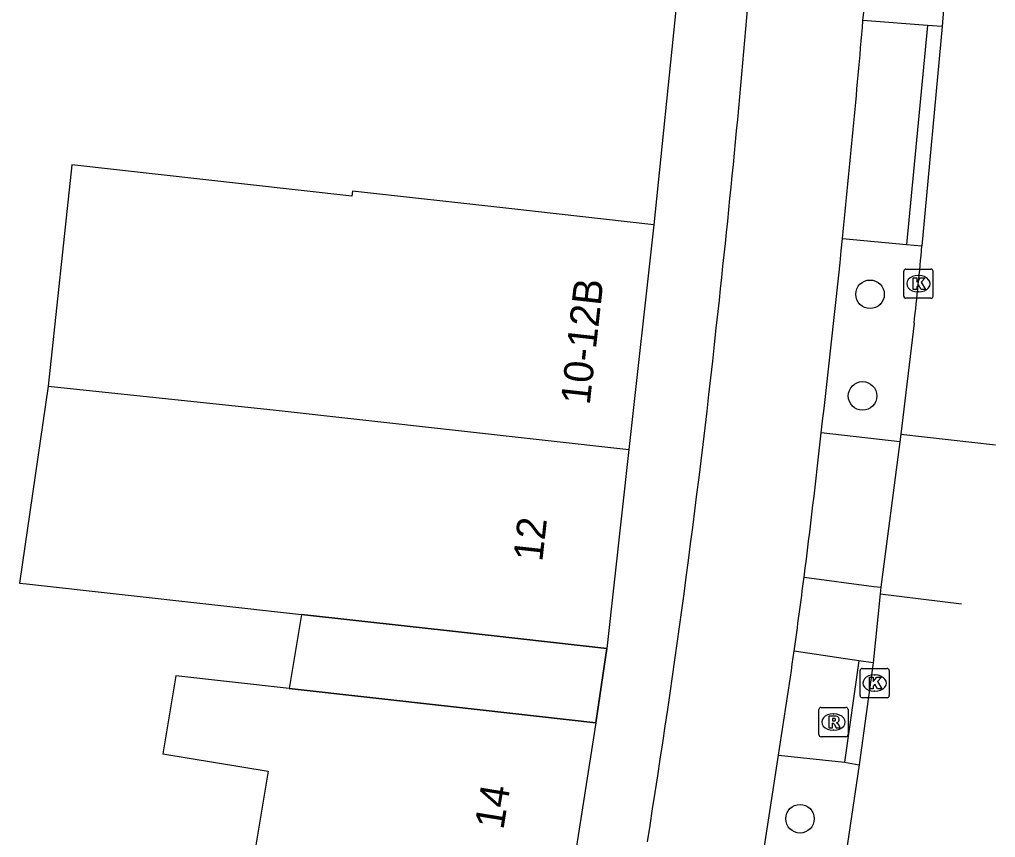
# Model space of a CAD drawing. Extents: x 161087 to 161922, y 382574 to 383873.
# Drawn here: x 161833.12 to 161866.52, y 382703.67 to 382731.66 of the extents above; entities that cross this region are included whole.
import ezdxf

# ---------------------------------------------------------------- set-up
doc = ezdxf.new("R2010")
doc.units = 0
for name, color, linetype in [('IMGEO_Berm_gesloten', 7, 'Continuous'), ('IMGEO_Berm_groen', 7, 'Continuous'), ('IMGEO_Berm_open', 7, 'Continuous'), ('IMGEO_Boom', 7, 'Continuous'), ('IMGEO_Fietspad_gesloten', 7, 'Continuous'), ('IMGEO_Kolk', 7, 'Continuous'), ('IMGEO_Pand', 7, 'Continuous'), ('IMGEO_Pand_nummerreeks', 7, 'Continuous'), ('IMGEO_Pand_overbouw', 7, 'Continuous'), ('IMGEO_Rijbaan_lokaal_gesloten', 7, 'Continuous'), ('IMGEO_Rijbaan_lokaal_open', 7, 'Continuous'), ('IMGEO_Rioolput', 7, 'Continuous'), ('IMGEO_Voetpad_open', 7, 'Continuous')]:
    doc.layers.add(name, color=color, linetype=linetype)

msp = doc.modelspace()

# ---------------------------------------------------------------- linework, layer by layer
at = {"layer": 'IMGEO_Berm_gesloten'}
for points in [[(161864.202, 382731.46), (161863.482, 382723.956)], [(161864.696, 382731.416), (161864.202, 382731.46)], [(161863.482, 382723.956), (161864.006, 382723.914)], [(161861.851, 382709.721), (161861.36, 382706.245)], [(161862.334, 382709.651), (161861.851, 382709.721)], [(161861.36, 382706.245), (161861.855, 382706.161)]]:
    msp.add_lwpolyline(points, dxfattribs=at)
at = {"layer": 'IMGEO_Berm_groen'}
for points in [[(161864.202, 382731.46), (161861.988, 382731.623)], [(161861.289, 382724.163), (161863.482, 382723.956)]]:
    msp.add_lwpolyline(points, dxfattribs=at)
at = {"layer": 'IMGEO_Berm_open'}
for points in [[(161863.253, 382717.214), (161860.56, 382717.514)], [(161859.973, 382712.583), (161862.359, 382712.264), (161862.605, 382712.233)], [(161861.851, 382709.721), (161859.633, 382710.052)], [(161859.099, 382706.489), (161861.36, 382706.245)]]:
    msp.add_lwpolyline(points, dxfattribs=at)
at = {"layer": 'IMGEO_Boom'}
for centre in [(161862.23, 382722.257), (161861.973, 382718.78), (161859.833, 382704.313)]:
    msp.add_circle(centre, 0.489, dxfattribs=at)
at = {"layer": 'IMGEO_Fietspad_gesloten'}
msp.add_lwpolyline([(161858.483, 382702.48), (161859.099, 382706.489)], dxfattribs=at)
for centre, radius, start, end in [((161450.001, 382766.972), 413.501, 355.09598, 355.73945), ((161443.323, 382767.161), 416.2, 353.72536, 355.4368), ((161429.341, 382768.399), 434.207, 354.15268, 355.14138), ((161419.334, 382769.255), 444.249, 353.31171, 354.17439), ((161515.74, 382757.93), 343.21, 350.8781, 353.93592), ((161529.822, 382754.385), 332.787, 352.78381, 353.63878), ((161621.237, 382743.365), 240.713, 352.04509, 352.65295), ((161657.287, 382738.557), 204.344, 350.97121, 351.98141)]:
    msp.add_arc(centre, radius, start, end, dxfattribs=at)
at = {"layer": 'IMGEO_Kolk'}
for p, q in [((161863.384, 382722.194), (161863.384, 382723.046)), ((161863.459, 382723.12), (161864.311, 382723.12)), ((161864.385, 382723.046), (161864.385, 382722.194)), ((161863.872, 382722.9), (161863.897, 382722.9)), ((161864.311, 382722.12), (161863.459, 382722.12)), ((161863.895, 382722.34), (161863.87, 382722.34)), ((161861.888, 382708.528), (161861.888, 382709.38)), ((161861.963, 382709.454), (161862.815, 382709.454)), ((161862.889, 382709.38), (161862.889, 382708.528)), ((161862.376, 382709.234), (161862.401, 382709.234)), ((161862.399, 382708.674), (161862.374, 382708.674)), ((161862.815, 382708.454), (161861.963, 382708.454))]:
    msp.add_line(p, q, dxfattribs=at)
for points in [[(161863.384, 382722.194), (161863.384, 382723.046)], [(161863.459, 382723.12), (161864.311, 382723.12)], [(161864.385, 382723.046), (161864.385, 382722.194)], [(161863.705, 382722.82), (161863.828, 382722.82), (161863.828, 382722.669), (161863.958, 382722.82), (161864.122, 382722.82), (161863.976, 382722.669), (161864.129, 382722.42), (161863.977, 382722.42), (161863.892, 382722.584), (161863.828, 382722.517), (161863.828, 382722.42), (161863.705, 382722.42), (161863.705, 382722.82)], [(161864.311, 382722.12), (161863.459, 382722.12)], [(161861.888, 382708.528), (161861.888, 382709.38)], [(161861.963, 382709.454), (161862.815, 382709.454)], [(161862.889, 382709.38), (161862.889, 382708.528)], [(161862.209, 382709.154), (161862.332, 382709.154), (161862.332, 382709.003), (161862.462, 382709.154), (161862.626, 382709.154), (161862.48, 382709.003), (161862.633, 382708.754), (161862.481, 382708.754), (161862.396, 382708.918), (161862.332, 382708.851), (161862.332, 382708.754), (161862.209, 382708.754), (161862.209, 382709.154)], [(161862.815, 382708.454), (161861.963, 382708.454)]]:
    msp.add_lwpolyline(points, dxfattribs=at)
for centre, start, end in [((161863.461, 382723.044), 91.552, 178.448), ((161863.461, 382723.044), 91.552, 178.448), ((161864.309, 382723.044), 1.552, 88.448), ((161864.309, 382723.044), 1.552, 88.448), ((161863.461, 382722.196), 181.552, 268.448), ((161863.461, 382722.196), 181.552, 268.448), ((161864.309, 382722.196), 271.552, 358.448), ((161864.309, 382722.196), 271.552, 358.448), ((161861.965, 382709.378), 91.552, 178.448), ((161861.965, 382709.378), 91.552, 178.448), ((161862.813, 382709.378), 1.552, 88.448), ((161862.813, 382709.378), 1.552, 88.448), ((161861.965, 382708.53), 181.552, 268.448), ((161861.965, 382708.53), 181.552, 268.448), ((161862.813, 382708.53), 271.552, 358.448), ((161862.813, 382708.53), 271.552, 358.448)]:
    msp.add_arc(centre, 0.0765, start, end, dxfattribs=at)
for centre, major_axis, ratio, start_param, end_param in [((161863.871, 382722.62), (-0.387, 0.002), 0.722429, 4.712389, 7.853982), ((161863.896, 382722.62), (-0.39, 0.002), 0.717154, 1.570796, 4.712389), ((161862.375, 382708.954), (-0.387, 0.002), 0.722429, 4.712389, 7.853982), ((161862.4, 382708.954), (-0.39, 0.002), 0.717154, 1.570796, 4.712389)]:
    msp.add_ellipse(centre, major_axis=major_axis, ratio=ratio, start_param=start_param, end_param=end_param, dxfattribs=at)
at = {"layer": 'IMGEO_Pand'}
for points in [[(161854.831, 382724.638), (161849.862, 382725.191), (161844.517, 382725.785), (161844.498, 382725.62), (161840.922, 382726.017), (161834.908, 382726.684), (161834.103, 382719.118)], [(161854.831, 382724.638), (161853.975, 382716.944)], [(161834.103, 382719.118), (161833.118, 382712.374), (161833.36, 382712.347), (161842.767, 382711.301), (161848.248, 382710.691), (161853.217, 382710.138)], [(161834.103, 382719.118), (161841.8, 382718.299), (161853.975, 382716.944)], [(161853.975, 382716.944), (161853.217, 382710.138)], [(161852.844, 382707.598), (161847.875, 382708.151), (161842.351, 382708.766), (161838.463, 382709.199), (161838.025, 382706.533), (161841.626, 382705.941), (161841.12, 382702.859)], [(161852.844, 382707.598), (161851.814, 382701.048)]]:
    msp.add_lwpolyline(points, dxfattribs=at)
at = {"layer": 'IMGEO_Pand_overbouw'}
msp.add_lwpolyline([(161852.844, 382707.598), (161853.217, 382710.138), (161848.248, 382710.691), (161842.767, 382711.301), (161842.351, 382708.766), (161847.875, 382708.151)], close=True, dxfattribs=at)
at = {"layer": 'IMGEO_Rijbaan_lokaal_gesloten'}
for points in [[(161865.365, 382740.966), (161864.916, 382734.182), (161864.696, 382731.416)], [(161864.696, 382731.416), (161864.006, 382723.914)], [(161863.737, 382721.269), (161863.287, 382717.469)], [(161863.287, 382717.469), (161866.524, 382717.11)], [(161862.582, 382712.012), (161862.334, 382709.651)], [(161862.582, 382712.012), (161865.358, 382711.665)], [(161862.334, 382709.651), (161861.855, 382706.161)], [(161861.855, 382706.161), (161861.244, 382702.01)]]:
    msp.add_lwpolyline(points, dxfattribs=at)
msp.add_arc((161780.577, 382731.063), 83.735, 353.28328, 355.10254, dxfattribs=at)
at = {"layer": 'IMGEO_Rijbaan_lokaal_open'}
for points in [[(161863.287, 382717.469), (161863.253, 382717.214)], [(161863.253, 382717.214), (161862.605, 382712.233)], [(161862.605, 382712.233), (161862.582, 382712.012)]]:
    msp.add_lwpolyline(points, dxfattribs=at)
at = {"layer": 'IMGEO_Rioolput'}
for p, q in [((161860.48, 382707.194), (161860.48, 382708.046)), ((161860.555, 382708.12), (161861.407, 382708.12)), ((161861.481, 382708.046), (161861.481, 382707.194)), ((161860.968, 382707.9), (161860.993, 382707.9)), ((161860.991, 382707.34), (161860.966, 382707.34)), ((161861.407, 382707.12), (161860.555, 382707.12))]:
    msp.add_line(p, q, dxfattribs=at)
for points in [[(161860.48, 382707.194), (161860.48, 382708.046)], [(161860.555, 382708.12), (161861.407, 382708.12)], [(161861.481, 382708.046), (161861.481, 382707.194)], [(161861.069, 382707.818), (161860.817, 382707.82), (161860.817, 382707.42)], [(161860.995, 382707.739), (161860.941, 382707.739), (161860.941, 382707.658)], [(161860.941, 382707.658), (161860.993, 382707.658)], [(161860.817, 382707.42), (161860.941, 382707.42), (161860.941, 382707.582), (161860.952, 382707.582)], [(161860.999, 382707.553), (161861.07, 382707.42), (161861.21, 382707.42), (161861.145, 382707.546)], [(161861.407, 382707.12), (161860.555, 382707.12)]]:
    msp.add_lwpolyline(points, dxfattribs=at)
for centre, radius, start, end in [((161860.557, 382708.044), 0.0765, 91.552, 178.448), ((161860.557, 382708.044), 0.0765, 91.552, 178.448), ((161861.405, 382708.044), 0.0765, 1.552, 88.448), ((161861.405, 382708.044), 0.0765, 1.552, 88.448), ((161860.977, 382707.847), 0.19, 274.7715, 282.9687), ((161861.001, 382707.643), 0.0964, 77.0061, 93.1865), ((161861.015, 382707.7), 0.0378, 276.6634, 79.6772), ((161861.068, 382707.708), 0.109, 350.3612, 89.416), ((161861.066, 382707.708), 0.112, 277.5842, 350.9817), ((161860.951, 382707.529), 0.0533, 26.0293, 88.6989), ((161861.05, 382707.493), 0.108, 29.5134, 73.7905), ((161860.557, 382707.196), 0.0765, 181.552, 268.448), ((161860.557, 382707.196), 0.0765, 181.552, 268.448), ((161861.405, 382707.196), 0.0765, 271.552, 358.448), ((161861.405, 382707.196), 0.0765, 271.552, 358.448)]:
    msp.add_arc(centre, radius, start, end, dxfattribs=at)
for centre, major_axis, ratio, start_param, end_param in [((161860.967, 382707.62), (-0.387, 0.002), 0.722429, 4.712389, 7.853982), ((161860.992, 382707.62), (-0.39, 0.002), 0.717154, 1.570796, 4.712389)]:
    msp.add_ellipse(centre, major_axis=major_axis, ratio=ratio, start_param=start_param, end_param=end_param, dxfattribs=at)
at = {"layer": 'IMGEO_Voetpad_open'}
for points in [[(161855.594, 382732.092), (161854.831, 382724.638)], [(161853.217, 382710.138), (161852.844, 382707.598)]]:
    msp.add_lwpolyline(points, dxfattribs=at)

# ---------------------------------------------------------------- texts
at = {"layer": 'IMGEO_Pand_nummerreeks'}
for s, rotation, p in [('10-12B', 83.6518, (161852.633, 382718.447)), ('12', 83.6485, (161851.01, 382713.086)), ('14', 80.7574, (161849.678, 382703.914))]:
    msp.add_text(s, height=1, rotation=rotation, dxfattribs=at).set_placement(p)

doc.saveas('drawing.dxf')
